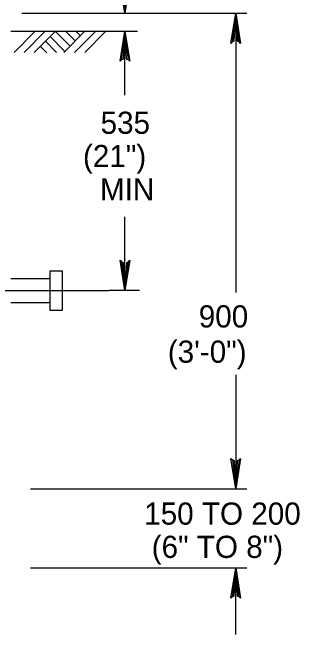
# Model space of a CAD drawing. Extents: x 638447 to 639352, y 298406 to 299000.
# Drawn here: x 638794 to 638837.5, y 298679.9 to 298774.1 of the extents above; entities that cross this region are included whole.
import ezdxf

# ---------------------------------------------------------------- set-up
doc = ezdxf.new("R2010")
doc.units = 0
for name, color, linetype in [('1', 7, 'Continuous'), ('2', 7, 'Continuous'), ('3', 7, 'Continuous')]:
    doc.layers.add(name, color=color, linetype=linetype)

msp = doc.modelspace()

# ---------------------------------------------------------------- linework, layer by layer
at = {"layer": '2'}
for p, q in [((638811.068375, 298784.084), (638811.068375, 298774.004)), ((638795.434375, 298774.004), (638812.986375, 298774.004)), ((638795.434375, 298774.004), (638826.962375, 298774.004)), ((638814.666375, 298774.004), (638829.552375, 298774.004)), ((638827.872375, 298774.004), (638827.872375, 298731.71925)), ((638793.754375, 298771.288), (638812.986375, 298771.288)), ((638794.264375, 298768.054), (638797.478375, 298771.268)), ((638795.454375, 298771.288), (638812.986375, 298771.288)), ((638795.768375, 298768.054), (638798.998375, 298771.286)), ((638797.322375, 298768.054), (638800.554375, 298771.286)), ((638799.708375, 298770.44), (638801.936375, 298768.21)), ((638800.484375, 298771.286), (638802.766375, 298769.004)), ((638801.798375, 298768.054), (638805.046375, 298771.304)), ((638802.040375, 298771.286), (638803.526375, 298769.8)), ((638803.440375, 298768.054), (638806.636375, 298771.252)), ((638803.612375, 298771.286), (638804.322375, 298770.578)), ((638804.994375, 298768.054), (638808.192375, 298771.252)), ((638811.068375, 298761.59025), (638811.068375, 298771.288)), ((638799.016375, 298769.748), (638800.710375, 298768.054)), ((638798.238375, 298768.97), (638799.206375, 298768.002)), ((638811.068375, 298732.004), (638811.068375, 298743.14825)), ((638793.754375, 298733.804), (638799.754375, 298733.804)), ((638708.694375, 298732.004), (638808.624375, 298732.004)), ((638813.264125, 298732.004), (638808.624375, 298732.004)), ((638793.754375, 298730.204), (638799.754375, 298730.204)), ((638827.872375, 298719.2515), (638827.872375, 298702.004)), ((638796.757125, 298702.004), (638829.552375, 298702.004)), ((638796.757125, 298690.004), (638829.552375, 298690.004)), ((638827.872375, 298679.924), (638827.872375, 298690.004))]:
    msp.add_line(p, q, dxfattribs=at)
for points in [[(638811.614375, 298778.362), (638811.300375, 298778.2), (638811.068375, 298774.004), (638811.614375, 298778.362), (638811.806375, 298778.586), (638811.068375, 298774.004), (638810.860375, 298778.198), (638810.548375, 298778.35), (638811.068375, 298774.004), (638810.340375, 298778.586), (638810.548375, 298778.35)], [(638827.326375, 298769.644), (638827.642375, 298769.808), (638827.872375, 298774.004), (638827.326375, 298769.644), (638827.134375, 298769.422), (638827.872375, 298774.004), (638828.080375, 298769.81), (638828.392375, 298769.658), (638827.872375, 298774.004), (638828.600375, 298769.422), (638828.392375, 298769.658)], [(638810.520375, 298766.93), (638810.836375, 298767.092), (638811.068375, 298771.288), (638810.520375, 298766.93), (638810.328375, 298766.706), (638811.068375, 298771.288), (638811.274375, 298767.096), (638811.588375, 298766.942), (638811.068375, 298771.288), (638811.796375, 298766.706), (638811.588375, 298766.942)], [(638811.614375, 298736.362), (638811.300375, 298736.2), (638811.068375, 298732.004), (638811.614375, 298736.362), (638811.806375, 298736.586), (638811.068375, 298732.004), (638810.860375, 298736.198), (638810.548375, 298736.35), (638811.068375, 298732.004), (638810.340375, 298736.586), (638810.548375, 298736.35)], [(638828.420375, 298706.362), (638828.104375, 298706.2), (638827.872375, 298702.004), (638828.420375, 298706.362), (638828.612375, 298706.586), (638827.872375, 298702.004), (638827.666375, 298706.198), (638827.354375, 298706.35), (638827.872375, 298702.004), (638827.144375, 298706.586), (638827.354375, 298706.35)], [(638827.326375, 298685.644), (638827.642375, 298685.808), (638827.872375, 298690.004), (638827.326375, 298685.644), (638827.134375, 298685.422), (638827.872375, 298690.004), (638828.080375, 298685.81), (638828.392375, 298685.658), (638827.872375, 298690.004), (638828.600375, 298685.422), (638828.392375, 298685.658)]]:
    msp.add_lwpolyline(points, dxfattribs=at)
msp.add_lwpolyline([(638799.754375, 298729.004), (638799.754375, 298735.004), (638801.554375, 298735.004), (638801.554375, 298729.004)], close=True, dxfattribs=at)

# ---------------------------------------------------------------- texts
at = {"layer": '1'}
for s, p in [('(3\'-0")', (638817.568375, 298721.06975)), ('(6" TO 8")', (638815.125875, 298691.5245))]:
    msp.add_text(s, height=3.36, dxfattribs=at).set_placement(p)
at = {"layer": '3'}
for s, height, p in [('535', 3.359988, (638807.379875, 298755.722)), ('(21")', 3.359988, (638804.708375, 298750.682)), ('MIN', 3.359988, (638807.287375, 298745.642)), ('900', 3.36, (638822.258875, 298726.40975)), ('150 TO 200', 3.36, (638813.990625, 298696.55575))]:
    msp.add_text(s, height=height, dxfattribs=at).set_placement(p)

doc.saveas('drawing.dxf')
